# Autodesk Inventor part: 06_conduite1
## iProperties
Created: 2002-11
Part Number: 06_conduite1
Material: ABS (plastique)
Document SubType Name: Modélisation
Designer: FIEVET
Control State: 0
Master: False
Checked Out: False
Shininess: 20.0
Length Units: 11269
Angle Units: 11279
Time Units: 11290
Mass Units: 11283
Length Display Precision: 3
Angle Display Precision: 2
Compacted: True
Density: 1.06
Volumn: 1.2923622145182656
Area: 26.412730968011466
PropertySet Name: Model Information
Author: FIEVET
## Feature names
1. Balayage1
